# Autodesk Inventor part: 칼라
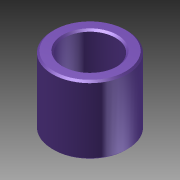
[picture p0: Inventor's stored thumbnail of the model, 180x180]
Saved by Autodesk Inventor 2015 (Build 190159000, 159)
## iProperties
Created: 2025-08
Part Number: 칼라
Material: 일반
Document SubType Name: Modeling
Designer: USER
Density: 1 g/cm^3
Appearance: 기본값
Author: USER
Author: jhkim
Creation Date: 2025-08-05
Sending System: Autodesk Inventor 2026
Preprocessor: ST-DEVELOPER v20.1
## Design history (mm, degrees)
node "칼라1"
node "솔리드1"
node "기준1"
